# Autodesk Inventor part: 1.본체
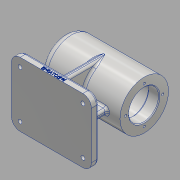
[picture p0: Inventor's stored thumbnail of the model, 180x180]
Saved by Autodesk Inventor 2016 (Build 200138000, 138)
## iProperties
Created: 2020-10
Part Number: 1.본체
Material: 알루미늄 6061
Document SubType Name: Modeling
Designer: user
Density: 2.7 g/cm^3
Appearance: 알루미늄 - 평지
Mass: 1026.28 g
Surface Area: 757.984 cm^2
Volume: 380.103 cm^3
Author: user
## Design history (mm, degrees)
sketch "스케치1"
  geometry: 1 further point
sketch "스케치2"
  geometry: L1 (0, 0)-(112, 0); L2 (0, 0)-(0, 34); L3 (0, 34)-(112, 34); L4 (112, 34)-(112, 0); L5 (6, 0)-(6, 10.5); L6 (6, 10.5)-(9, 10.5); L7 (9, 10.5)-(9, 16); L8 (9, 16)-(13, 16); L9 (13, 16)-(13, 17.5); L10 (13, 17.5)-(31, 17.5); L11 (97, 21)-(112, 21); L12 (31, 17.5)-(31, 21); L13 (31, 21)-(43, 21); L14 (43, 21)-(43, 24); L15 (43, 24)-(97, 24); L16 (97, 24)-(97, 21)
  constraints: 32 end point, 11 perpendicular, 3 vertical, 2 point on line, 1 horizontal
  dimensions: "d0" = 68 diameter of L3 L1; "d1" = 42 diameter of L11 L1; "d2" = 21 diameter of L6 L1; "d3" = 32 diameter of L8 L1; "d4" = 35 diameter of L10 L1; "d5" = 42 diameter of L13 L1; "d6" = 48 diameter of L15 L1; "d7" = 15 distance of L11.start L11.end; "d8" = 54 distance of L14.end L15.end; "d9" = 12 distance of L12.end L13.end; "d10" = 18 distance of L9.end L10.end; "d11" = 4 distance of L7.end L8.end; "d12" = 3 distance of L5.end L6.end; "d13" = 112 distance of L1.start L1.end
revolve "회전1" sketch "스케치2" stored, may be unused: angle "d14" = 90 deg
sketch "스케치3"
  geometry: L1 (0, -64)-(112, -64); L2 (112, -64)-(112, -74); L3 (112, -74)-(0, -74); L4 (0, -74)-(0, -64); L5 (0, -34)-(0, 34) reference; 2 further points
  constraints: 8 end point, 2 parallel, 1 horizontal, 1 midpoint, 1 perpendicular, 1 vertical alignment
  dimensions: "d15" = 112 distance of L2.end L3.end; "d16" = 10 distance of L1.end L2.end; "d18" = 74 distance of L3.end point (0, 0)
extrude "돌출1" join sketch "스케치3" stored distance "d19" = 90; taper "d20" = 0 deg
sketch "스케치4"
  geometry: L1 (112, 0)-(112, 90) reference; L2 (0, 0)-(112, 0) reference; L3 (0, 0)-(0, 90) reference; L4 (112, 90)-(0, 90) reference; L5 (0, 45)-(112, 45); L6 (18, 49)-(94, 49); L7 (94, 49)-(94, 41); L8 (94, 41)-(18, 41); L9 (18, 41)-(18, 49); L10 (18, 49)-(94, 41); L11 (94, 49)-(18, 41); L12 (52, 79)-(60, 79); L13 (60, 79)-(60, 11); L14 (60, 11)-(52, 11); L15 (52, 11)-(52, 79); L16 (52, 79)-(60, 11); L17 (60, 79)-(52, 11); 3 further points
  constraints: 26 end point, 7 midpoint, 4 parallel, 2 horizontal, 2 perpendicular
  dimensions: "d22" = 76 distance of L7.end L8.end; "d23" = 8 distance of L6.end L7.end; "d24" = 56 distance from line of L1 point (56, 45); "d25" = 45 distance from line of L4 point (56, 45); "d26" = 8 distance of L12.start L12.end; "d27" = 68 distance of L14.end L12.start
extrude "돌출2" join sketch "스케치4" stored distance "d28" = 90; taper "d29" = 0 deg
fillet "모깎기1" dims "d30" = 12
sketch "스케치5"
  geometry: A1 r 12 centre (0, 78) between (0, 90) and (-12, 78) reference; A2 r 12 centre (88, 78) between (100, 78) and (88, 90) reference; A3 r 12 centre (88, 12) between (88, 0) and (100, 12) reference; A4 r 12 centre (0, 12) between (-12, 12) and (0, 0) reference; 1 further point
hole "구멍1" sketch "스케치5" at (0, 78), (0, 12), (88, 12), (88, 78) diameter "d31" = 5.5; stored, may be unused: countersink angle "d35" = 90 deg, drill point angle "d37" = 118 deg; dims "d32" = 6, "d33" = 9.5, "d34" = 5.4, "d36" = 8
sketch "스케치6"
  geometry: L1 (0, 0)-(0, 26)
  constraints: 2 end point, 1 vertical
  dimensions: "d38" = 26 distance of L1.start L1.end
hole "구멍2" sketch "스케치6" at (0, 26) diameter "d39" = 3.242; stored, may be unused: countersink angle "d43" = 90 deg, drill point angle "d45" = 118 deg; dims "d40" = 8, "d41" = 9.5, "d42" = 5.4, "d44" = 11
fillet "모깎기2" dims "d49" = 3
fillet "모깎기3" dims "d50" = 0.3
fillet "모깎기4" dims "d51" = 3
chamfer "모따기1" distance "d52" = 1; stored, may be unused: second distance "d53" = 2, angle "d54" = 45 deg
fillet "모깎기5" dims "d55" = 10
fillet "모깎기6" dims "d56" = 3
fillet "모깎기7" dims "d57" = 3
fillet "모깎기8" dims "d58" = 3
sketch "스케치7"
  geometry: L1 (23.478, -69.461)-(88.522, -69.461); L2 (88.522, -69.461)-(88.522, -72.539); L3 (88.522, -72.539)-(23.478, -72.539); L4 (23.478, -72.539)-(23.478, -69.461); L5 (23.478, -71)-(56, -71); L6 (56, -69.461)-(56, -71); L7 (12, -74)-(100, -74) reference; L8 (112, -74)-(112, -67) reference; 1 further point
  constraints: 4 end point, 2 midpoint, 2 other
  dimensions: "d59" = 3 distance from line of L7 L5.end; "d60" = 56 distance from line of L8 L5.end
feature "엠보싱1" sketch "스케치7" dims "d15" = 112, "d16" = 10, "d18" = 74, "d61" = 0.5, "d62" = 0
node "솔리드1"
pattern_circular "원형 패턴1" dims angle "d47" = 360 deg
node "투영된 루프1"
